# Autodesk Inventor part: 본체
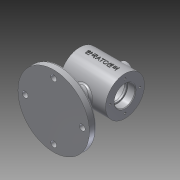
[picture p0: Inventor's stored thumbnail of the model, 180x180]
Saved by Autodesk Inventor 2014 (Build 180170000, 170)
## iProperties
Created: 2018-12
Part Number: 본체
Material: 알루미늄 6061
Document SubType Name: Modeling
Designer: 601-22
Density: 2.71 g/cm^3
Appearance: 알루미늄 - 평지
Mass: 687.609 g
Surface Area: 555.719 cm^2
Volume: 253.73 cm^3
Author: 601-22
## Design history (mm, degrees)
sketch "스케치1"
  geometry: L1 (0, 0)-(70, 0); L2 (0, 0)-(70, 0); L3 (70, 0)-(70, 30); L4 (70, 30)-(0, 30); L5 (0, 30)-(0, 0)
  constraints: 10 end point, 2 horizontal, 2 parallel, 1 perpendicular
  dimensions: "d0" = 70 distance of L1.start L1.end; "d1" = 30 distance between parallel lines of L2 L4
revolve "회전1" sketch "스케치1" stored, may be unused: angle "d2" = 90 deg
sketch "스케치2"
  geometry: L1 (0, -30)-(0, 30) reference; L2 (70, -30)-(70, 30) reference; L3 (0, 0)-(70, 0); L4 (0, 0)-(12, 0); L5 (12, 0)-(12, 16); L6 (11.7, 16)-(0, 16); L7 (0, 16)-(0, 0); L8 (12, 0)-(15, 0); L9 (15, 0)-(15, 14); L10 (15, 14)-(12, 14); L11 (12, 15.7)-(12, 0); L12 (15, 0)-(55, 0); L13 (55, 0)-(55, 22); L14 (52, 25)-(18, 25); L15 (15, 22)-(15, 0); L16 (55, 0)-(58, 0); L17 (58, 0)-(58, 15.7); L18 (58, 14)-(55, 14); L19 (55, 14)-(55, 0); L20 (58, 0)-(70, 0); L21 (70, 0)-(70, 16); L22 (70, 16)-(58.3, 16); L23 (58, 16)-(58, 0); A1 r 3 centre (18, 22) between (18, 25) and (15, 22); A2 r 3 centre (52, 22) between (55, 22) and (52, 25); A3 r 0.3 centre (11.7, 15.7) between (12, 15.7) and (11.7, 16); A4 r 0.3 centre (58.3, 15.7) between (58.3, 16) and (58, 15.7); 2 further points
  constraints: 42 end point, 10 parallel, 8 point on circle, 8 point on line, 8 tangent, 6 perpendicular, 5 horizontal, 4 centre point, 1 equal radius, 1 midpoint
  dimensions: "d3" = 12 distance of L6.end L5.end; "d4" = 3 distance of L10.end L9.end; "d5" = 40 distance of point (15, 25) point (55, 25); "d6" = 3 distance of L18.end L18.start; "d7" = 12 distance of L23.start L21.end; "d8" = 16 distance between parallel lines of L3 L6; "d9" = 14 distance between parallel lines of L3 L10; "d10" = 25 distance between parallel lines of L12 L14; "d11" = 14 distance between parallel lines of L16 L18; "d12" = 16 distance between parallel lines of L20 L22; "d13" = 3 radius of A1; "d14" = 3 radius of A2; "d83" = 0.3 radius of A3
revolve "회전2" sketch "스케치2" stored, may be unused: angle "d15" = 90 deg
node "작업 평면3"
sketch "스케치5"
  geometry: L1 (0, 30)-(0, -30) reference; L2 (-70, 30)-(-70, -30) reference; L3 (0, -30)-(-70, -30) reference; L4 (0, 30)-(-70, 30) reference; L5 (0, 0)-(-70, 0); L6 (-35, -30)-(-35, 30); C1 r 55 at (-35, 0)
  constraints: 4 end point, 4 midpoint, 1 centre point
  dimensions: "d25" = 110 diameter of C1
extrude "돌출1" join sketch "스케치5" distance "d26" = 11; taper "d27" = 0 deg
sketch "스케치6"
  geometry: L1 (90, -64)-(-20, -64) reference; L2 (0, -30)-(70, -30) reference; L3 (35, -27.651)-(35, -64); L4 (-20, -64)-(23, -52.478); L5 (23, -52.478)-(23, -27.651); L6 (23, -27.651)-(35, -27.651); L7 (-20, -64)-(35, -64); 1 further point
  constraints: 10 end point, 2 perpendicular, 1 collinear, 1 midpoint, 1 parallel
  dimensions: "d28" = 15 deg angle of L1 L4; "d29" = 12 distance between parallel lines of L5 L3; "d30" = 55 distance from line of L1.end L3
revolve "회전3" sketch "스케치6" stored, may be unused: angle "d31" = 90 deg
node "작업 평면4"
sketch "스케치7"
  geometry: L1 (-32.072, 11.637)-(-37.928, 11.637) reference; L2 (-37.928, -11.637)-(-32.072, -11.637) reference; L3 (0, 30)-(0, -30) reference; L4 (-70, 30)-(-70, -30) reference; L5 (0, 0)-(-70, 0); L6 (-35, 0)-(-35, -23.091); C1 r 10 at (-35, 0)
  constraints: 4 end point, 2 midpoint, 2 vertical alignment, 1 centre point, 1 coincident, 1 perpendicular
  dimensions: "d33" = 20 diameter of C1
extrude "돌출2" join sketch "스케치7" stored distance "d34" = 11; taper "d35" = 0 deg
sketch "스케치8"
  geometry: C1 r 10 at (0, 0) reference; C2 r 5 at (0, 0); 1 further point
  constraints: 1 centre point, 1 coincident
  dimensions: "d36" = 10 diameter of C2
extrude "돌출3" cut sketch "스케치8" distance "d37" = 25; taper "d38" = 0 deg
chamfer "모따기1" distance "d39" = 1; stored, may be unused: second distance "d40" = 2, angle "d41" = 45 deg
fillet "모깎기1" dims "d42" = 3
sketch "스케치10" dims "d43" = 46
  geometry: L1 (0, 0)-(0, 27.65); C1 r 17 at (0, 0) reference; 1 further point
  constraints: 2 end point, 1 coincident, 1 point on line, 1 vertical, 1 vertical alignment, 2 other
hole "구멍1" sketch "스케치10" at (0, 23) diameter "d44" = 3.242; stored, may be unused: countersink angle "d48" = 90 deg, drill point angle "d50" = 118 deg; dims "d45" = 8, "d46" = 4, "d47" = 2, "d49" = 10
node "작업 평면5"
node "작업 평면7"
node "작업 평면8"
sketch "스케치13" dims "d67" = 88
  geometry: L1 (-35, 0)-(-35, 48.388); C1 r 55 at (-35, 0) reference; 2 further points
  constraints: 2 end point, 1 coincident, 1 point on line, 1 vertical, 1 vertical alignment, 2 other
hole "구멍3" sketch "스케치13" at (-35, 44) diameter "d68" = 9; stored, may be unused: countersink angle "d72" = 90 deg, drill point angle "d74" = 0 deg; dims "d69" = 8, "d70" = 14, "d71" = 10, "d73" = 20
node "작업 평면9"
sketch "스케치14"
  geometry: L1 (0, 30)-(70, 30) reference; L2 (35, 30)-(35, -18.358); L3 (10.368, 3.602)-(59.632, 3.602); L4 (59.632, 3.602)-(59.632, -3.602); L5 (59.632, -3.602)-(10.368, -3.602); L6 (10.368, -3.602)-(10.368, 3.602); 3 further points
  constraints: 3 midpoint, 2 end point, 1 perpendicular, 2 other
  dimensions: "d79" = 30 distance from line of point (59.632, 0) L1; "d80" = 0 distance from line of L2 point (35, 3.602)
feature "엠보싱1" sketch "스케치14" dims "d1" = 30, "d81" = 0.5, "d82" = 0
node "솔리드1"
pattern_circular "원형 패턴1" dims angle "d52" = 360 deg
mirror "대칭1"
pattern_circular "원형 패턴2" dims angle "d76" = 360 deg
node "투영된 루프1"
node "투영된 루프2"
node "투영된 루프3"
other parameters: "d24" = -75, "d32" = 37, "d54" = 35, "d66" = -55
